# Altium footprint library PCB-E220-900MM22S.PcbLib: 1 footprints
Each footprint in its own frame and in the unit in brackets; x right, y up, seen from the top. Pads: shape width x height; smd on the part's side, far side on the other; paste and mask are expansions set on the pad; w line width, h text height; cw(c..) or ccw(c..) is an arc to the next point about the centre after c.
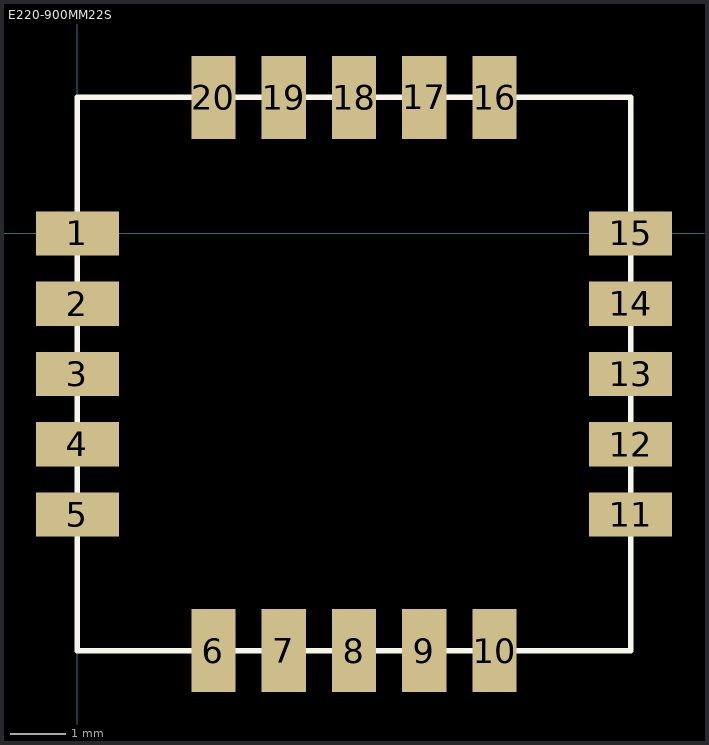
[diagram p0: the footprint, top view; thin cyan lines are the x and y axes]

## E220-900MM22S [mm]
height 2.5
pads (20):
  rect 1.5x0.8 smd mask+0.102: 1(0,0) 2(0,-1.27) 3(0,-2.54) 4(0,-3.81) 5(0,-5.08) 11(10,-5.08) 12(10,-3.81) 13(10,-2.54) 14(10,-1.27) 15(10,0)
  rect 0.8x1.5 smd mask+0.102: 6(2.46,-7.54) 7(3.73,-7.54) 8(5,-7.54) 9(6.27,-7.54) 10(7.54,-7.54) 16(7.54,2.46) 17(6.27,2.46) 18(5,2.46) 19(3.73,2.46) 20(2.46,2.46)
Top Overlay:
  lines w0.1: 0,-7.54 10,-7.54 10,2.46 0,2.46 0,-7.54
